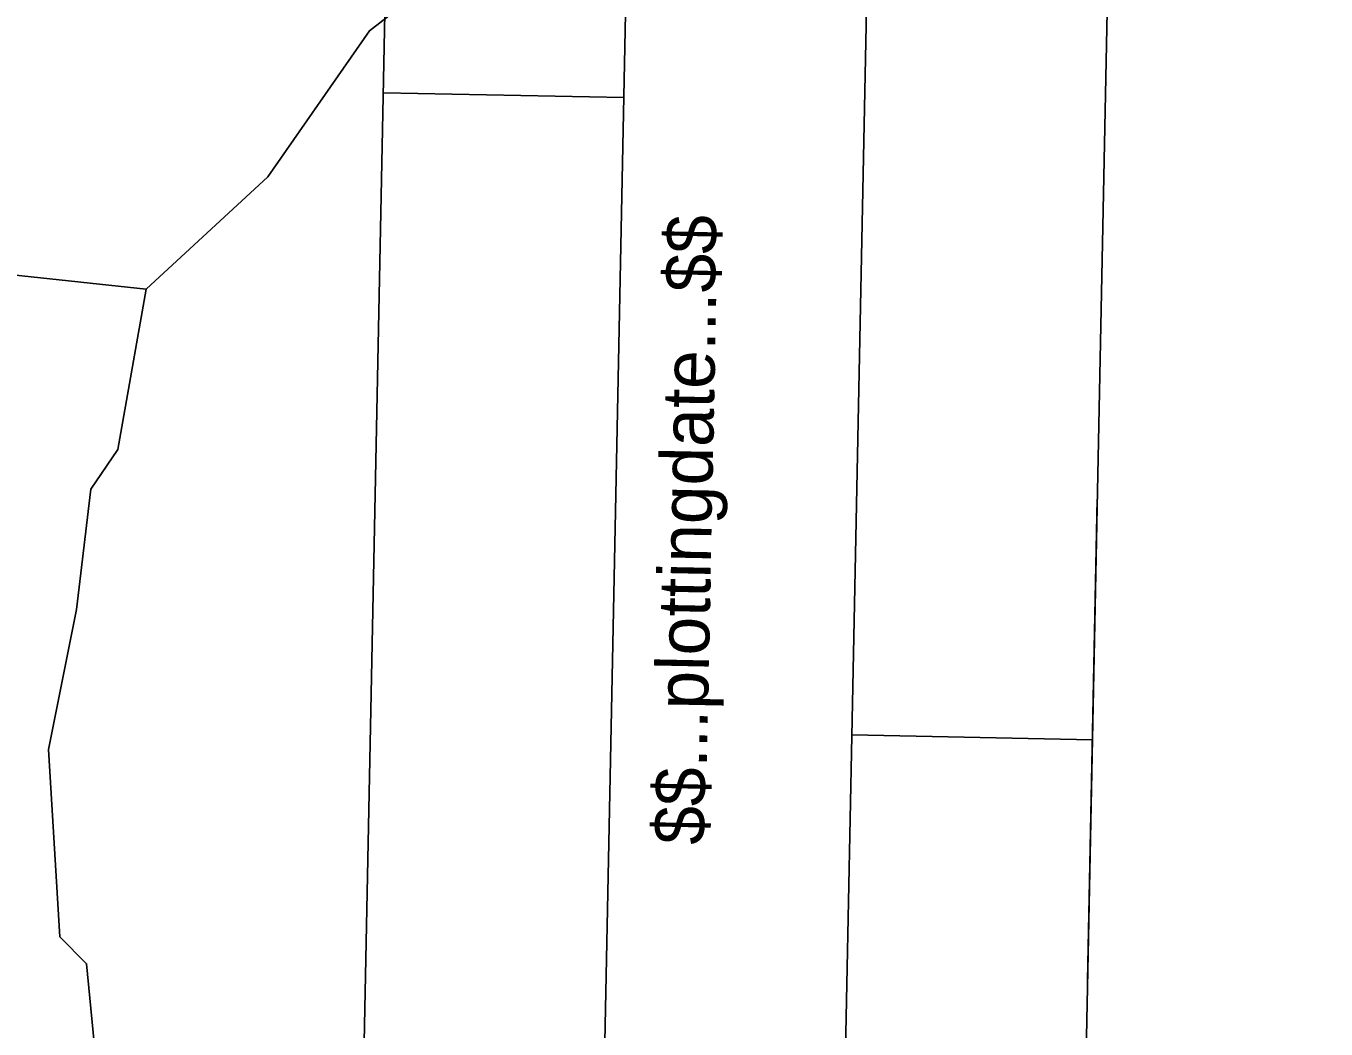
# Model space of a CAD drawing. Extents: x 331323 to 388339, y 121519 to 205315.
# Drawn here: x 366865 to 368485, y 140129 to 141380 of the extents above; entities that cross this region are included whole.
import ezdxf

# ---------------------------------------------------------------- set-up
doc = ezdxf.new("R2010")
doc.units = 0
for name, color, linetype in [('Level 57', 7, 'Continuous'), ('P_RDWY_Text', 7, 'Continuous'), ('PLT_Sheet_Border', 7, 'Continuous'), ('PLT_Sheet_Info', 7, 'Continuous')]:
    doc.layers.add(name, color=color, linetype=linetype)

msp = doc.modelspace()

# ---------------------------------------------------------------- linework, layer by layer
at = {"layer": 'Level 57'}
for points in [[(367014.6, 141051.6), (367166.1, 141191.9), (367292.8, 141374.1), (367696, 141687.1), (367771.8, 141761.4), (367857, 141960.7), (367874.5, 142043.8), (367928, 142418.4), (367979.1, 142534.6), (368080.5, 142683.7), (368282.1, 142840.2), (368676.4, 143086.6), (369005.2, 143475.3), (369619.6, 144078.1), (370015, 144449.5), (370611, 144869.2), (370778.7, 144967.6), (370812.1, 144967.3)], [(364906.3, 142137.4), (365005.8, 142069.8), (365546.9, 141964.9), (365646.4, 141897.3), (366171.4, 141859.3), (366245.9, 141791.9), (366491.8, 141331.3), (366656.8, 141138.2), (366848, 141069.8), (367014.6, 141051.6)], [(366907.1, 140244.2), (366892.6, 140477.7), (366927.6, 140652.4), (366945.6, 140802.2), (366979.4, 140851.9), (367014.6, 141051.6)], [(366907.1, 140244.2), (366940.2, 140210.6), (366955.4, 140052.1), (366988.1, 139985.1), (367035.4, 139684.7), (367213.5, 139108.1), (367236.6, 138899.5), (367318.2, 138698.8), (367417, 138556.2), (367681.2, 138270.5), (367771.2, 138086.3), (367834.3, 137694.1), (367933.8, 137626.5), (368233.7, 137590.5), (368324.8, 137523), (368390.2, 137380.7), (368778.5, 136985.5), (369580.4, 136219.9), (370688.4, 135176.5), (371812.8, 134116.3), (371829.2, 134082.8)]]:
    msp.add_lwpolyline(points, dxfattribs=at)
at = {"layer": 'P_RDWY_Text'}
msp.add_lwpolyline([(354790.8, 130527.7), (355201.6, 150923.5), (368398.9, 150657.7), (367988.1, 130261.9)], close=True, dxfattribs=at)
at = {"layer": 'PLT_Sheet_Border'}
for points in [[(367988.1, 130261.9), (368398.9, 150657.7), (355201.6, 150923.5), (354790.8, 130527.7)], [(367691.1, 130411.9), (368091, 150267.9), (355493.5, 150521.6), (355093.6, 130665.6)]]:
    msp.add_lwpolyline(points, close=True, dxfattribs=at)
at = {"layer": 'PLT_Sheet_Info'}
for p, q in [((367103.6, 131038.8), (367484.2, 149935)), ((367403.5, 131032.8), (367784.1, 149929)), ((367610.1, 141290.7), (367310.2, 141296.8)), ((368188.1, 140189.8), (368200.1, 140789.7)), ((368194.1, 140489.7), (367894.2, 140495.8))]:
    msp.add_line(p, q, dxfattribs=at)

# ---------------------------------------------------------------- texts
msp.add_text('$$...plottingdate...$$', height=64.8, rotation=88.8462, dxfattribs=at).set_placement((367711.4, 140358.5))

doc.saveas('drawing.dxf')
